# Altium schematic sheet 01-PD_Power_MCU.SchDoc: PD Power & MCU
size A2; Date: Mon 1st Aug, 2020; CompanyName: RGT Supply and Service Ltd.; Engineer: Nattawut; Address1: 285/95 M.3 T.Tonpao Sankampaeng; Address2: Chiangmai 50130 Thailand Tel.+66 89 1645339; Revision: 1.5; SheetNumber: 1; SheetTotal: 4; ContentRev1: Original Document; dateREV1: 01-01-2023; NameRev1: Nattawut; NameRev3: Nattawut; NameRev2: Nattawut; NameRev4: Nattawut; NameRev5: Nattawut; NameRev6: Nattawut; dateREV2: 20-04-2023; dateREV3: 04-11-2023; dateREV4: 14-05-2024; dateREV5: 05-07-2024; dateREV6: 16-09-2024; ContentRev2: Change to AD controller; ContentRev3: Update Power Coupling; ContentRev4: Improve for EMC ability; ContentRev5: Add D31, Replace FB7 to R164; ContentRev6: Improve for EMC ability; Rev1: 1.0; Rev2: 1.1; Rev3: 1.2; Rev4: 1.3; Rev5: 1.4; Rev6: 1.5; Project: PoDL; PageSetup: Record=PageOptions¦CenterHorizontal=True¦CenterVertical=True¦PrintScale=0.73¦XCorrection=1.00¦YCorrection=1.00¦PrintKind=0¦BorderSize=5000000¦LeftOffset=0¦BottomOffset=0¦Orientation=2¦PaperLength=1000¦PaperWidth=1000¦Scale=100¦PaperSource=7¦PrintQuality=-3¦MediaType=1¦DitherType=10¦PrintScaleMode=1¦PaperKind=A3¦PaperIndex=8
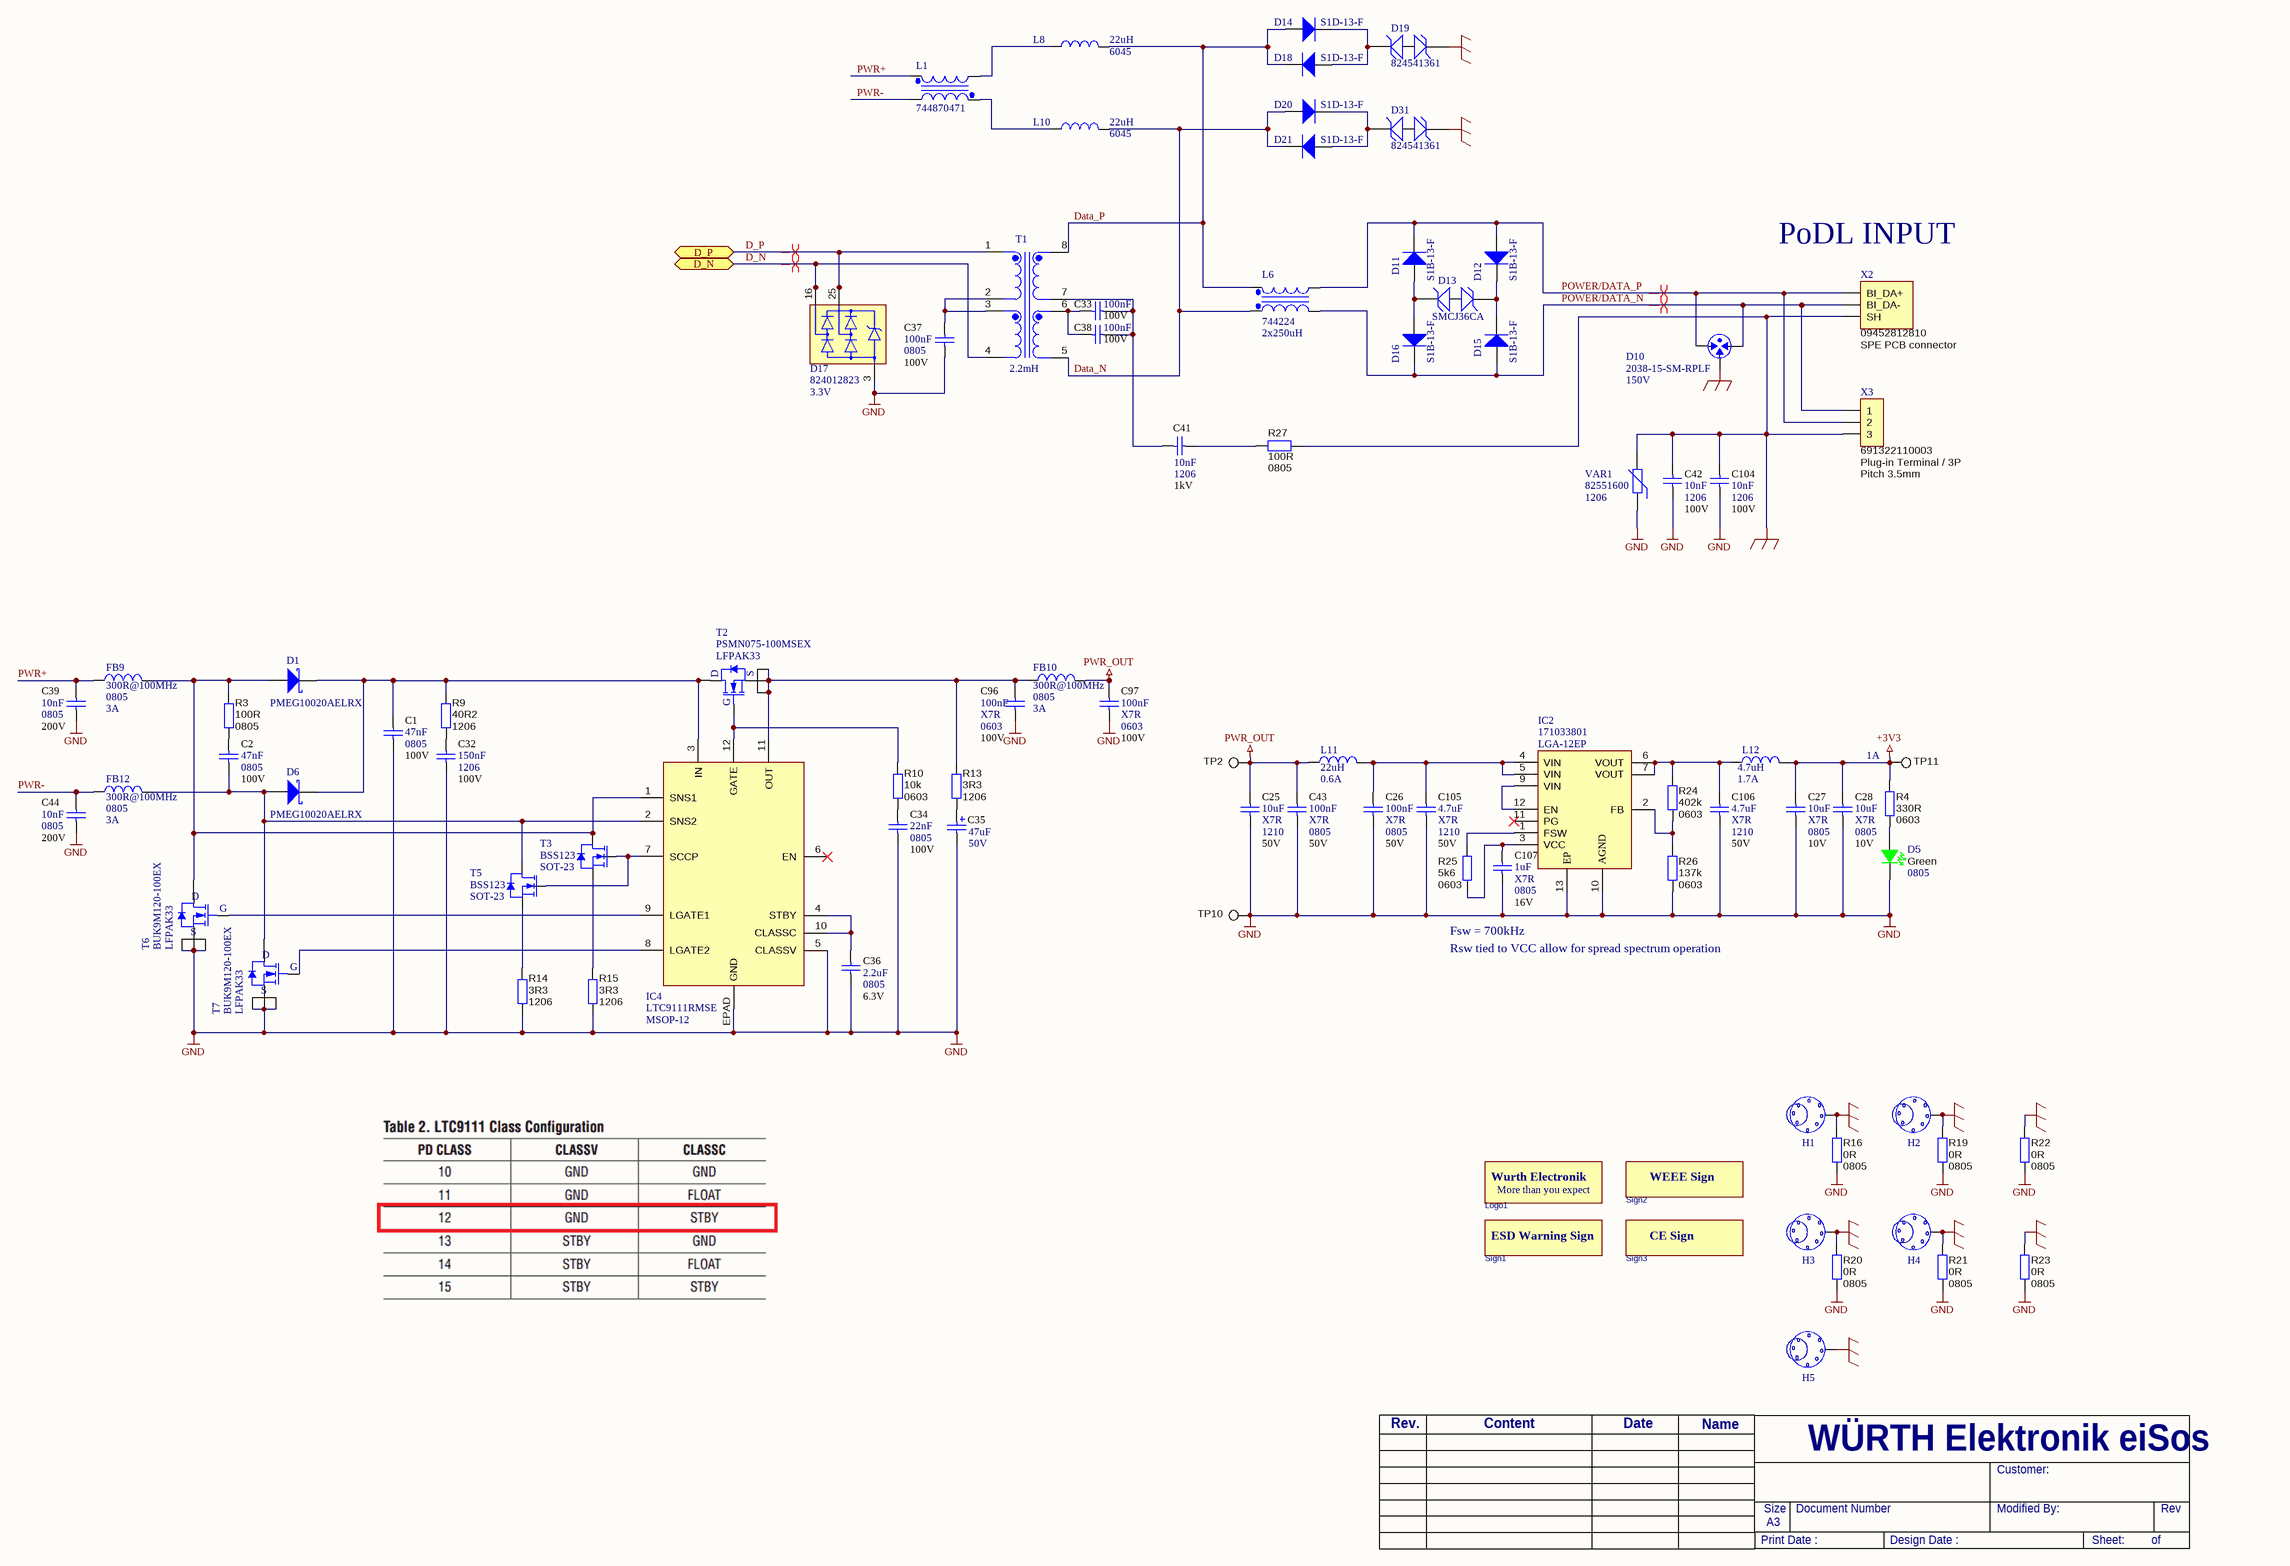
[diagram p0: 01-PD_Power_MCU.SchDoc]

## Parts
C1  value 47nF  VDC_V: 100V  PackageReference: 0805  [CC2012-0805]  (hidden comment: 885012207126)
C2  value 47nF  VDC_V: 100V  PackageReference: 0805  [CC2012-0805]  (hidden comment: 885012207126)
C25  value 10uF  VDC_V: 50V  PackageReference: 1210  Dielectric: X7R  [CC3225-1210]  (hidden comment: 885012209073)
C26  value 100nF  VDC_V: 50V  PackageReference: 0805  Dielectric: X7R  [CC2012-0805]  (hidden comment: 885012207098)
C27  value 10uF  VDC_V: 10V  PackageReference: 0805  Dielectric: X7R  [CC2012-0805]  (hidden comment: 885012207026)
C28  value 10uF  VDC_V: 10V  PackageReference: 0805  Dielectric: X7R  [CC2012-0805]  (hidden comment: 885012207026)
C32  value 150nF  PackageReference: 1206  VDC_V: 100V  [CC3216-1206]  (hidden comment: 885012208119)
C33  value 100nF  VDC_V: 100V  [CC1608-0603]  (hidden comment: 885012206120)
C34  value 22nF  VDC_V: 100V  PackageReference: 0805  [CC2012-0805]  (hidden comment: 885012207124)
C35  value 47uF  VDC_V: 50V  [SMT 6.3mmx7.7mm - WE]  (hidden comment: 865080645012)
C36  value 2.2uF  VDC_V: 6.3V  PackageReference: 0805  [CC2012-0805]  (hidden comment: 885012207001)
C37  value 100nF  VDC_V: 100V  PackageReference: 0805  [CC2012-0805]  (hidden comment: 885012207128)
C38  value 100nF  VDC_V: 100V  [CC1608-0603]  (hidden comment: 885012206120)
C39  value 10nF  VDC_V: 200V  PackageReference: 0805  [CC2012-0805]  (hidden comment: 885342207005)
C41  value 10nF  PackageReference: 1206  VDC_V: 1kV  [CC3216-1206]  (hidden comment: 885342208021)
C42  value 10nF  PackageReference: 1206  VDC_V: 100V  [CC3216-1206]  (hidden comment: 885012208112)
C43  value 100nF  VDC_V: 50V  PackageReference: 0805  Dielectric: X7R  [CC2012-0805]  (hidden comment: 885012207098)
C44  value 10nF  VDC_V: 200V  PackageReference: 0805  [CC2012-0805]  (hidden comment: 885342207005)
C96  value 100nF  VDC_V: 100V  PackageReference: 0603  Dielectric: X7R  [CC1608-0603]  (hidden comment: 885012206120)
C97  value 100nF  VDC_V: 100V  PackageReference: 0603  Dielectric: X7R  [CC1608-0603]  (hidden comment: 885012206120)
C104  value 10nF  PackageReference: 1206  VDC_V: 100V  [CC3216-1206]  (hidden comment: 885012208112)
C105  value 4.7uF  VDC_V: 50V  PackageReference: 1210  Dielectric: X7R  [CC3225-1210]  (hidden comment: 885012209048)
C106  value 4.7uF  VDC_V: 50V  PackageReference: 1210  Dielectric: X7R  [CC3225-1210]  (hidden comment: 885012209048)
C107  value 1uF  VDC_V: 16V  PackageReference: 0805  Dielectric: X7R  [CC2012-0805]  (hidden comment: 885012207051)
D1  PMEG10020AELRX  [SOD-123FL]
D5  value Green  PackageReference: 0805  [LED2012 (0805) - Green]  (hidden comment: 150080VS75000)
D6  PMEG10020AELRX  [SOD-123FL]
D10  value 150V  [2038-xx]  (hidden comment: 2038-15-SM-RPLF)
D11  S1B-13-F  [SMA/DO-214AC]
D12  S1B-13-F  [SMA/DO-214AC]
D13  SMCJ36CA  [SMC/DO-214AB]
D14  S1D-13-F  [SMA/DO-214AC]
D15  S1B-13-F  [SMA/DO-214AC]
D16  S1B-13-F  [SMA/DO-214AC]
D17  Voltage: 3.3V  [DFN1210-6L 1.2X1.0]  (hidden comment: 824012823)
D18  S1D-13-F  [SMA/DO-214AC]
D19  824541361  [SMC/DO-214AB]
D20  S1D-13-F  [SMA/DO-214AC]
D21  S1D-13-F  [SMA/DO-214AC]
D31  824541361  [SMC/DO-214AB]
FB9  value 300R@100MHz  PackageReference: 0805  I DC: 3A  [CF2012-0805]  (hidden comment: 742792031)
FB10  value 300R@100MHz  PackageReference: 0805  I DC: 3A  [CF2012-0805]  (hidden comment: 742792031)
FB12  value 300R@100MHz  PackageReference: 0805  I DC: 3A  [CF2012-0805]  (hidden comment: 742792031)
H1  Hole M3 with Vias  [M3_VIA]  (value not drawn)
H2  Hole M3 with Vias  [M3_VIA]  (value not drawn)
H3  Hole M3 with Vias  [M3_VIA]  (value not drawn)
H4  Hole M3 with Vias  [M3_VIA]  (value not drawn)
H5  Hole M3 with Vias  [M3_VIA]  (value not drawn)
IC2  PackageReference: LGA-12EP  [MAGI³C-VDRM_LGA-12EP]  (hidden comment: 171033801)
IC4  value LTC9111RMSE  PackageReference: MSOP-12  [MSOP-12 PAD]  (hidden comment: LTC9111RMSE#PBF)
L1  PartNumber: 744870471  [Inductor_WE-DD 1280]  (hidden comment: 744870471_(2))
L6  value 2x250uH  [Inductor_WE-SL2]  (hidden comment: 744224)
L8  value 22uH  PackageReference: 6045  [Inductor_WE-LQS 6045]  (hidden comment: 74404064220)
L10  value 22uH  PackageReference: 6045  [Inductor_WE-LQS 6045]  (hidden comment: 74404064220)
L11  value 22uH  I DC: 0.6A  [Inductor_WE-LQS 3015]  (hidden comment: 74404032220)
L12  value 4.7uH  I DC: 1.7A  [Inductor_WE-LQS-4018]  (hidden comment: 74404042047)
Logo1  Wurth_994x400  [Wurth_994x400]  (value not drawn)  (no BOM)
R3  value 100R  PackageReference: 0805  [CR2012-0805]  (hidden comment: 560112120020)
R4  value 330R  PackageReference: 0603  [CR1608-0603]  (hidden comment: 560112116020)
R9  value 40R2  PackageReference: 1206  [CR3216-1206]  (hidden comment: RC1206FR-0740R2L)
R10  value 10k  PackageReference: 0603  [CR1608-0603]  (hidden comment: 560112116005)
R13  value 3R3  PackageReference: 1206  [CR3216-1206]  (hidden comment: RC1206FR-073R3L)
R14  value 3R3  PackageReference: 1206  [CR3216-1206]  (hidden comment: RC1206FR-073R3L)
R15  value 3R3  PackageReference: 1206  [CR3216-1206]  (hidden comment: RC1206FR-073R3L)
R16  value 0R  PackageReference: 0805  [CR2012-0805]  (hidden comment: RC0805JR-070RL)
R19  value 0R  PackageReference: 0805  [CR2012-0805]  (hidden comment: RC0805JR-070RL)
R20  value 0R  PackageReference: 0805  [CR2012-0805]  (hidden comment: RC0805JR-070RL)
R21  value 0R  PackageReference: 0805  [CR2012-0805]  (hidden comment: RC0805JR-070RL)
R22  value 0R  PackageReference: 0805  [CR2012-0805]  (hidden comment: RC0805JR-070RL)
R23  value 0R  PackageReference: 0805  [CR2012-0805]  (hidden comment: RC0805JR-070RL)
R24  value 402k  PackageReference: 0603  [CR1608-0603]  (hidden comment: RC0603FR-07402KL)
R25  value 5k6  PackageReference: 0603  [CR1608-0603]  (hidden comment: 560112116017)
R26  value 137k  PackageReference: 0603  [CR1608-0603]  (hidden comment: RC0603FR-07137KL)
R27  value 100R  PackageReference: 0805  [CR2012-0805]  (hidden comment: 560112120020)
Sign1  ESD_380x350  [ESD_380x351]  (value not drawn)  (no BOM)
Sign2  WEEE_275x400  [WEEE_275x400]  (value not drawn)  (no BOM)
Sign3  CE_412x295  [CE_412x295]  (value not drawn)  (no BOM)
T1  Ind_H: 2.2mH  [749070011_WE-PoDL]  (hidden comment: 749070011)
T2  PackageReference: LFPAK33  [LFPAK33 (SOT1210)]  (hidden comment: PSMN075-100MSEX)
T3  value BSS123  [SOT-23]  (hidden comment: BSS123LT1G)
T5  value BSS123  [SOT-23]  (hidden comment: BSS123LT1G)
T6  PackageReference: LFPAK33  [LFPAK33 (SOT1210)]  (hidden comment: BUK9M120-100EX)
T7  PackageReference: LFPAK33  [LFPAK33 (SOT1210)]  (hidden comment: BUK9M120-100EX)
TP2  (no value)  [TESTPOINT 1.5mm]
TP10  (no value)  [TESTPOINT 1.5mm]
TP11  (no value)  [TESTPOINT 1.5mm]
VAR1  PackageReference: 1206  [CV3216-1206]  (hidden comment: 82551600)
X2  value SPE PCB connector  [09452812810]  (hidden comment: 09452812810)
X3  value Plug-in Terminal / 3P  PackageReference: Pitch 3.5mm  [691322110003]  (hidden comment: 691322110003)

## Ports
D_N (bidir), D_P (bidir)

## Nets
+3V3: C27.1 C28.1 L12.2 R4.1 TP11.1
GND: C1.2 C25.2 C26.2 C27.2 C28.2 C32.2 C34.2 C35.2 C36.2 C37.2 C39.2 C42.2 C43.2 C44.2 C96.2 C97.2 C104.2 C105.2 C106.2 C107.2 D5.1 D17.3(GND) IC2.10(AGND) IC2.13(EP) IC4.5(CLASSV) IC4.EPAD(GND) R14.2 R15.2 R16.1 R19.1 R20.1 R21.1 R22.1 R23.1 R26.2 T6.1(S) T6.2(S) T6.3(S) T7.1(S) T7.2(S) T7.3(S) TP10.1 VAR1.1
PWR_OUT: C25.1 C43.1 C97.1 FB10.2 L11.1 TP2.1
SHIELD: C42.1 C104.1 D10.3 D19.1(A) D31.1(A) H1.0(Hole) H2.0(Hole) H3.0(Hole) H4.0(Hole) H5.0(Hole) R16.2 R19.2 R20.2 R21.2 R22.2 R23.2 R27.2 VAR1.2 X2.SH X3.3
D_N: D17.1(IO1) D17.6(IO1) T1.4 ; port D_N
D_P: D17.2(IO2) D17.5(IO2) T1.1 ; port D_P
Data_N: D20.1(A) D21.2(K) L6.1(L1) L10.2 T1.5
Data_P: D14.1(A) D18.2(K) L6.2(L2) L8.2 T1.8
POWER/DATA_N: D10.2 D15.1(A) D16.2(K) L6.4(L1') X2.2(BI_DA-) X3.1
POWER/DATA_P: D10.1 D11.2(K) D12.1(A) L6.3(L2') X2.1(BI_DA+) X3.2
PWR+: C39.1 FB9.1 L1.1(L1)
PWR-: C44.1 FB12.1 L1.4(L2')
NetC1_1: C1.1 D1.2(K) D6.2(K) IC4.3(IN) R9.1 T2.mb(D)
NetC2_1: C2.1 R3.2
NetC2_2: C2.2 D6.1(A) FB12.2 IC4.2(SNS2) T5.3(D) T7.mb(D)
NetC26_1: C26.1 C105.1 IC2.4(VIN) IC2.5(VIN) L11.2
NetC32_1: C32.1 R9.2
NetC33_1: C33.1 C38.1 T1.6
NetC33_2: C33.2 C38.2 C41.1 T1.7
NetC34_1: C34.1 R10.2
NetC35_1: C35.1 R13.2
NetC36_1: C36.1 IC4.4(STBY) IC4.10(CLASSC)
NetC37_1: C37.1 T1.2 T1.3
NetC41_2: C41.2 R27.1
NetC96_1: C96.1 FB10.1 IC4.11(OUT) R13.1 T2.1(S) T2.2(S) T2.3(S)
NetC106_1: C106.1 IC2.6(VOUT) IC2.7(VOUT) L12.1 R24.2
NetC107_1: C107.1 IC2.3(VCC) R25.2
NetD1_1: D1.1(A) FB9.2 IC4.1(SNS1) R3.1 T3.3(D) T6.mb(D)
NetD5_2: D5.2 R4.2
NetD11_1: D11.1(A) D13.2(K) D16.1(A)
NetD12_2: D12.2(K) D13.1(A) D15.2(K)
NetD14_2: D14.2(K) D18.1(A) D19.2(K)
NetD20_2: D20.2(K) D21.1(A) D31.2(K)
NetIC2_1: IC2.1(FSW) R25.1
NetIC2_2: IC2.2(FB) R24.1 R26.1
NetIC2_9: IC2.9(VIN) IC2.12(EN)
NetIC4_7: IC4.7(SCCP) T3.1(G) T5.1(G)
NetIC4_8: IC4.8(LGATE2) T7.4(G)
NetIC4_9: IC4.9(LGATE1) T6.4(G)
NetIC4_12: IC4.12(GATE) R10.1 T2.4(G)
NetL1_2: L1.2(L2) L10.1
NetL1_3: L1.3(L1') L8.1
NetR14_1: R14.1 T5.2(S)
NetR15_1: R15.1 T3.2(S)

Not connected (* = marked no-connect by the designer): IC2 11(PG)*; IC4 6(EN)*

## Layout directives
differential pair: D_N, D_P, POWER/DATA_N, POWER/DATA_P

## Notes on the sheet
- (near X2) PoDL INPUT
- 1A
- Fsw = 700kHz
- Rsw tied to VCC allow for spread spectrum operation
- Rev.
- Content
- Date
- Name
- WÜRTH Elektronik eiSos
- Customer:
- Print Date :
- Size
- A3
- Document Number
- Design Date :
- Modified By:
- Sheet:
- of
- Rev

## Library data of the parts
C1 C2 = 885012207126: CAP, CERM, 47nF, 100V, +/-10%, X7R, 0805; Manufacturer: Wurth; Polarized: N; TaMax_C: 125; TaMin_C: -55; Tolerance_%: 10; CompType: Capacitor
C25 = 885012209073: CAP, CERM, 10uF, 50V, +/-10%, X7R, 1210; Manufacturer: Wurth; Polarized: N; TaMax_C: 125; TaMin_C: -55; Tolerance_%: 10%; CompType: Capacitor
C26 C43 = 885012207098: CAP, CERM, 100nF, 50V, +/-10%, X7R, 0805; Manufacturer: Wurth; Polarized: N; TaMax_C: 125; TaMin_C: -55; Tolerance_%: 10; CompType: Capacitor
C27 C28 = 885012207026: CAP, CERM, 10uF, 10V, +/-10%, X7R, 0805; Manufacturer: Wurth; Polarized: N; TaMax_C: 125; TaMin_C: -55; Tolerance_%: 10; CompType: Capacitor
C32 = 885012208119: CAP, CERM, 150nF, 100V, +/-10%, X7R, 1206; Manufacturer: Wurth; Polarized: N; TaMax_C: 125; TaMin_C: -55; Tolerance_%: 10; CompType: Capacitor
C33 C38 C96 C97 = 885012206120: CAP, CERM, 100nF, 100V, +/-10%, X7R, 0603; Manufacturer: Wurth; Polarized: N; TaMax_C: 125; TaMin_C: -55; Tolerance_%: 10; CompType: Capacitor
C34 = 885012207124: CAP, CERM, 22nF, 100V, +/-10%, X7R, 0805; Manufacturer: Wurth; Polarized: N; TaMax_C: 125; TaMin_C: -55; Tolerance_%: 10; CompType: Capacitor
C35 = 865080645012: CAP, ECAP, 47uF, 50V, +/-20%, 6.3mm x 7.7mm; Manufacturer: Wurth; ESR_Ohm: -Ohm; IRMS_A: 0.23A; Polarized: Y; TaMax_C: 105; TaMin_C: -55; Tolerance_%: 20; CompType: Capacitor
C36 = 885012207001: CAP, CERM, 2.2uF, 6.3V, +/-10%, X7R, 0805; Manufacturer: Wurth; Polarized: N; TaMax_C: +125; TaMin_C: -55; Tolerance_%: 10; CompType: Capacitor
C37 = 885012207128: CAP, CERM, 100nF, 100V, +/-10%, X7R, 0805; Manufacturer: Wurth; Polarized: N; TaMax_C: 125; TaMin_C: -55; Tolerance_%: 10; CompType: Capacitor
C39 C44 = 885342207005: CAP, CERM, 10nF, 200V, +/-10%, X7R, 0805; Manufacturer: Wurth; Polarized: N; TaMax_C: 125; TaMin_C: -55; Tolerance_%: 10; CompType: Capacitor
C41 = 885342208021: CAP, CERM, 10nF, 1kV, +/-10%, X7R, 1206; Manufacturer: Wurth; Polarized: N; TaMax_C: 125; TaMin_C: -55; Tolerance_%: 10; CompType: Capacitor
C42 C104 = 885012208112: CAP, CERM, 10nF, 100V, +/-10%, X7R, 1206; Manufacturer: Wurth; Polarized: N; TaMax_C: 125; TaMin_C: -55; Tolerance_%: 10; CompType: Capacitor
C105 C106 = 885012209048: CAP, CERM, 4.7uF, 50V, +/-10%, X7R, 1210; Manufacturer: Wurth; Polarized: N; TaMax_C: 125; TaMin_C: -55; Tolerance_%: 10%; CompType: Capacitor
C107 = 885012207051: CAP, CERM, 1uF, 16V, +/-10%, X7R, 0805; Manufacturer: Wurth; Polarized: N; TaMax_C: 125; TaMin_C: -55; Tolerance_%: 10; CompType: Capacitor
D1 D6 = PMEG10020AELRX: DIODE, Schottky, 100V, 2A, SOD-123W; Manufacturer: Nexperia
D5 = 150080VS75000: LED 570NM GREEN 0805 SMD; Manufacturer: Wurth
D10 = 2038-15-SM-RPLF: Gas Discharge Tubes, 150V, 1pF, 5x7.5mm, SMD; Manufacturer: Bourns
D11 D12 D15 D16 = S1B-13-F: DIODE, Rectifiers, 100V, 1A, SMA; Manufacturer: Diodes
D13 = SMCJ36CA: DIODE, TVS , 36V, 1.5kW, Bidirection, SMC; Manufacturer: Onsemi; Power: 1500W
D14 D18 D20 D21 = S1D-13-F: DIODE, Rectifiers, 200V, 1A, SMA; Manufacturer: Diodes
D17 = 824012823: DIODE, TVS Super Speed , 3.3V, DFN1210-6L; Manufacturer: Wurth
D19 D31 = 824541361: DIODE, TVS , 36V, 1.5kW, Bidirection, SMC; Manufacturer: Wurth; Power: 1500W
FB9 FB10 FB12 = 742792031: Ferrite Bead 300R @ 100MHz / 0805 / 3.0A; Manufacturer: Wurth
H1-H5 = Hole M3 with Vias: SAP: xxxx
IC2 = 171033801: IC REG BUCK, ADJ, 3A, LGA-16EP; Manufacturer: Wurth
IC4 = LTC9111RMSE#PBF: IC SPoE PD, 10Base-T1L, 2.3-60V, MSOP-12; Manufacturer: Analog Devices
L1 = 744870471_(2): Coupled Inductor 2x470uH / 12.5x12.5mm /0.7A; Manufacturer: Wurth; Rdc: 2x1.0; I DC: 0.7A
L6 = 744224: Common Mode Chokes 2x250uH / 9.2x6mm / 1200mA; Manufacturer: Wurth; Rdc: 0.13; I DC: 1.2A
L8 L10 = 74404064220: Inductor 22uH / 6045 / 2.1A; Manufacturer: Wurth
L11 = 74404032220: Inductor 22uH / 3015 / 0.6A; Manufacturer: Wurth
L12 = 74404042047: Inductor 4.7uH / 4018 / 1.7A; Manufacturer: Wurth
R3 R27 = 560112120020: RES, 100 ohm, 1%, 0.125W, 0805; Manufacturer: Wurth; CompType: Resistor; Power_W: 0.125
R4 = 560112116020: RES, 330 ohm, 1%, 0.1W, 0603; Manufacturer: Wurth; CompType: Resistor; Power_W: 0.1
R9 = RC1206FR-0740R2L: RES, 40.2 ohm, 1%, 0.25W, 1206; Manufacturer: Yageo; CompType: Resistor; Power_W: 0.25
R10 = 560112116005: RES, 10kohm, 1%, 0.1W, 0603; Manufacturer: Wurth; CompType: Resistor; Power_W: 0.1
R13-R15 = RC1206FR-073R3L: RES, 3.3 ohm, 1%, 0.25W, 1206; Manufacturer: Yageo; CompType: Resistor; Power_W: 0.25
R16 R19-R23 = RC0805JR-070RL: RES, 0 ohm, -%, 0.125W, 0805; Manufacturer: Yageo; CompType: Resistor; Power_W: 0.125
R24 = RC0603FR-07402KL: RES, 402kohm, 1%, 0.1W, 0603; Manufacturer: Yageo; CompType: Resistor; Power_W: 0.1
R25 = 560112116017: RES, 5.6kohm, 1%, 0.1W, 0603; Manufacturer: Wurth; CompType: Resistor; Power_W: 0.1
R26 = RC0603FR-07137KL: RES, 137kohm, 1%, 0.1W, 0603; Manufacturer: Yageo; CompType: Resistor; Power_W: 0.1
T1 = 749070011: Trans, PoDL, 2.2mH, SMT; Manufacturer: Wurth; CompType: Transformer; Ns1toNp: 1:1
T2 = PSMN075-100MSEX: MOSFET, N-CH, 100V, 18A, LFPAK33; Manufacturer: Nexperia
T3 T5 = BSS123LT1G: MOSFET, N-CH, 100V, 0.17A, SOT-23; Manufacturer: Onsemi
T6 T7 = BUK9M120-100EX: MOSFET, N-CH, 100V, 11.5A, LFPAK33; Manufacturer: Nexperia
TP2 TP10 TP11 = TP / 1.5mm: Test Point, SMT, Miniature; Value: 1.5mm
VAR1 = 82551600: Varistor, 85Vdc, 60Vac, 160pF, 1206; Manufacturer: Wurth
X2 = 09452812810: CON, SPE, 2P, Shield, 4A, R/A, INS; Manufacturer: HARTING; CompType: Connector
X3 = 691322110003: CON, Terminal Block, Plug-in, 3P, P3.5mm, 10A, R/A, INS; Manufacturer: Wurth; CompType: Connector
